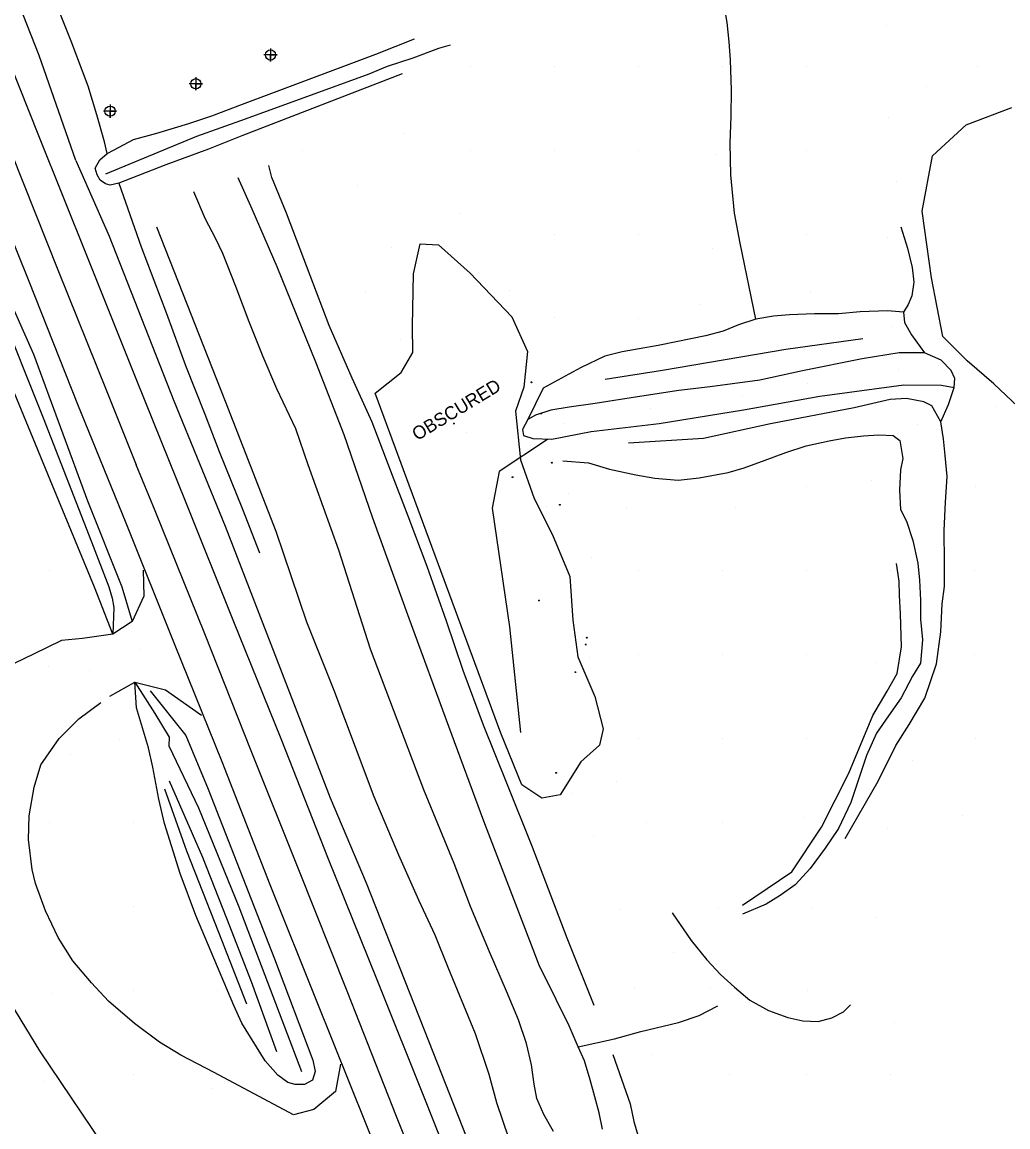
# Model space of a CAD drawing. Extents: x 524772 to 528246, y 273285 to 283088.
# Drawn here: x 527735.4 to 527849.8, y 274392.5 to 274520.7 of the extents above; entities that cross this region are included whole.
import ezdxf

# ---------------------------------------------------------------- set-up
doc = ezdxf.new("R2010")
doc.units = 0
for name, color, linetype in [('Exist DTM Breakline', 7, 'Continuous'), ('Exist DTM Crownline', 7, 'Continuous'), ('Exist DTM Regular Point CELL', 7, 'Continuous'), ('Exist Roads EOP', 7, 'Continuous'), ('Exist Roads Soil', 7, 'Continuous'), ('PH Exist DTM Breakline', 7, 'Continuous'), ('PH Exist DTM Obscure Area', 7, 'Continuous'), ('PH Exist DTM Obscure Area Text', 7, 'Continuous'), ('PH Exist DTM Point', 7, 'Continuous')]:
    doc.layers.add(name, color=color, linetype=linetype)

# ---------------------------------------------------------------- blocks, each defined once
blk = doc.blocks.new('EXIST DTM REGULAR POINT')
at = {"layer": 'Exist DTM Regular Point CELL'}
blk.add_lwpolyline([(0, 0.00152), (0, -0.00152), (0, 0), (0.00152, 0), (-0.00152, 0)], dxfattribs=at)
blk.add_circle((0, 0), 0.00119, dxfattribs=at)

msp = doc.modelspace()

# ---------------------------------------------------------------- linework, layer by layer
at = {"layer": 'Exist DTM Breakline'}
for points in [[(527796.38, 274472.24), (527790.75, 274468.51), (527789.94, 274464.27)], [(527789.94, 274464.27), (527791.97, 274450.5), (527793.25, 274438.22)]]:
    msp.add_lwpolyline(points, dxfattribs=at)
at = {"layer": 'Exist DTM Crownline'}
for points in [[(527645.29, 274728.71), (527650.66, 274714.78), (527656.2, 274701.14), (527661.92, 274686.83), (527667.92, 274671.8), (527673.23, 274658.53), (527678.79, 274644.52), (527684.53, 274630.14), (527690.01, 274616.33), (527695.81, 274601.85), (527701.46, 274587.58), (527706.7, 274574.49), (527712.09, 274560.76), (527717.61, 274547.05), (527723.18, 274532.85), (527728.56, 274519.55), (527734.18, 274505.53), (527739.64, 274491.72), (527745.18, 274477.97), (527748.66, 274469.27)], [(527812.62, 274309.15), (527807.09, 274323.12), (527801.45, 274337.52), (527795.99, 274351.2), (527790.12, 274365.72), (527784.37, 274379.82), (527778.84, 274393.65), (527773.12, 274408.21), (527767.53, 274422.3), (527762, 274436.08), (527756.61, 274449.67), (527750.87, 274463.93), (527748.66, 274469.27)]]:
    msp.add_lwpolyline(points, dxfattribs=at)
at = {"layer": 'Exist Roads EOP'}
for points in [[(527748.73, 274479.07), (527743.01, 274493.36), (527737.36, 274507.44), (527731.71, 274521.56), (527726.71, 274534.12), (527721.09, 274548.21), (527715.44, 274562.4), (527710.05, 274576.02), (527704.67, 274589.46), (527699.11, 274603.25), (527693.43, 274617.43), (527687.81, 274631.65), (527682.17, 274645.88), (527676.6, 274659.84), (527670.89, 274674.09), (527665.32, 274688.05), (527659.56, 274702.45), (527654.06, 274716.02), (527648.34, 274730.37)], [(527808.82, 274308.77), (527803.4, 274322.05), (527797.76, 274336.55), (527792.33, 274350.25), (527786.57, 274364.63), (527781, 274378.67), (527775.35, 274392.79), (527769.66, 274406.93), (527764.22, 274420.54), (527758.62, 274434.8), (527753.2, 274448.32), (527747.5, 274462.52), (527741.9, 274476.29), (527736.23, 274490.54), (527730.55, 274504.58)], [(527863.89, 274191.51), (527862.12, 274195.56), (527861.19, 274196.14), (527859.74, 274198.94), (527854.35, 274213.12), (527848.92, 274227.38), (527843.58, 274240.81), (527838, 274255.12), (527832.68, 274268.57), (527827.21, 274282.4), (527821.56, 274296.66), (527815.92, 274310.87), (527810.35, 274324.86), (527804.78, 274338.91), (527799.29, 274352.72), (527793.54, 274366.95), (527787.87, 274381.23), (527782.28, 274395.33), (527776.62, 274409.52), (527770.97, 274423.52), (527765.47, 274437.47), (527760, 274451.08), (527754.4, 274465.08), (527748.73, 274479.07)]]:
    msp.add_lwpolyline(points, dxfattribs=at)
at = {"layer": 'Exist Roads Soil'}
for points in [[(527749.48, 274457.07), (527749.53, 274454.03), (527748.19, 274451.11), (527745.95, 274449.62), (527742.42, 274449.14)], [(527745.62, 274442.45), (527748.5, 274444.07), (527752.05, 274443.17), (527756.22, 274440.23)], [(527772.34, 274399.73), (527771.78, 274396.58), (527769.28, 274394.47), (527766.92, 274393.87)]]:
    msp.add_lwpolyline(points, dxfattribs=at)
at = {"layer": 'PH Exist DTM Breakline'}
for points in [[(527741.66, 274504.6), (527737.42, 274516.78), (527732.32, 274529.71), (527724.98, 274549.13), (527719.16, 274564.36), (527715.63, 274574.32), (527714.55, 274578.02), (527714.19, 274580.1), (527714.39, 274581.73), (527715.05, 274582.71), (527716.82, 274583.67), (527718.28, 274584.2), (527720.91, 274585.38), (527723.64, 274586.58)], [(527745.28, 274505.39), (527744.98, 274506.77), (527744.1, 274509.9), (527743.08, 274513.22), (527741.13, 274518.46), (527738.24, 274525.64), (527734.35, 274535.54), (527730.94, 274544.61), (527727.68, 274553.41), (527726.25, 274556.28), (527724.49, 274560.38), (527723.03, 274564.1), (527720.19, 274571.56), (527718.74, 274575.3), (527717.87, 274577.77), (527716.43, 274581.79), (527718.46, 274581.99), (527720.51, 274582.88), (527722.97, 274584.16), (527725.86, 274585.71)], [(527820.55, 274486.19), (527818.7, 274495.02), (527818.05, 274498.49), (527817.62, 274502.95), (527817.57, 274506.62), (527817.67, 274509.73), (527817.72, 274512.76), (527817.58, 274516.27), (527817.43, 274518.35), (527817.22, 274520.62), (527816.77, 274523.11), (527816.33, 274524.99), (527814.49, 274529.02), (527811.56, 274528.34), (527809.89, 274528.93), (527808.04, 274529.6), (527806.16, 274530.8), (527805.12, 274532.08), (527803.75, 274534.22), (527803, 274535.66), (527802.46, 274537.88), (527802.67, 274539.74), (527803.88, 274542.26), (527804.37, 274544.34)], [(527779.53, 274514.64), (527760.92, 274507.45), (527757.06, 274505.92), (527752.1, 274504.09), (527746.66, 274501.98), (527745.64, 274501.75), (527745.09, 274501.87), (527744.5, 274502.33), (527744.15, 274502.92), (527743.9, 274503.72), (527744.43, 274504.68), (527745.28, 274505.39), (527746.1, 274505.85), (527748.34, 274507.02), (527751.07, 274507.78), (527754.75, 274508.9), (527757.45, 274509.78), (527761.01, 274511.14), (527776.46, 274516.94), (527780.96, 274518.72)], [(527785.06, 274517.97), (527783.71, 274517.6), (527780.75, 274516.49), (527777.79, 274515.5), (527775.63, 274514.62), (527761.29, 274509.4), (527755.66, 274507.4), (527745.1, 274503.01)], [(527741.66, 274504.6), (527745.51, 274495.8), (527753.01, 274476.72), (527758.97, 274462.16), (527764.73, 274447.27), (527771.16, 274430.65), (527775.35, 274420.77), (527782.56, 274402.44), (527787.94, 274388.77), (527793.91, 274373.37), (527798.61, 274361.95), (527803.2, 274350.89), (527807.64, 274339.89), (527811.88, 274328.63), (527815.94, 274318.47), (527823.29, 274299.84), (527830.72, 274280.05), (527835.27, 274267.52), (527840.2, 274254.37)], [(527801.79, 274406.55), (527798.66, 274414.34), (527794.62, 274424.93), (527791.66, 274432.35), (527788.96, 274439.07), (527786.57, 274445.41), (527784.66, 274451.14), (527782.4, 274457.48), (527780.19, 274463.33), (527778.19, 274468.53), (527776.05, 274474.22), (527773.73, 274479.33), (527771.03, 274485.44), (527768.84, 274491.27), (527766.08, 274498.5), (527764.4, 274502.64), (527764.05, 274504.02)], [(527802.76, 274392.18), (527802.36, 274394.1), (527801.86, 274395.95), (527801.32, 274397.92), (527800.65, 274400.11), (527799.93, 274401.75), (527798.87, 274404.17), (527797.37, 274407.23), (527795.41, 274411.22), (527793.44, 274416.38), (527789, 274427.94), (527784.94, 274438.9), (527780.34, 274451.46), (527776.1, 274463.08), (527772.77, 274472.77), (527769.5, 274481.21), (527765, 274492.25), (527762.11, 274498.93), (527760.49, 274502.59)], [(527746.66, 274501.98), (527749.24, 274494.57), (527752.19, 274486.83), (527754.37, 274480.79), (527756.62, 274475.16), (527758.3, 274470.84), (527761, 274464.14), (527762.98, 274459.08)], [(527797.08, 274391.94), (527795.95, 274393.91), (527795.15, 274395.76), (527794.82, 274397.43), (527794.5, 274399.65), (527793.93, 274402.14), (527793, 274404.89), (527791.62, 274408.2), (527789.66, 274412.77), (527787.44, 274418.02), (527785.56, 274423.03), (527782.03, 274431.58), (527775.85, 274447.88), (527772.15, 274459.36), (527768.61, 274469.3), (527767.17, 274473.46), (527764.99, 274478.09), (527763.38, 274481.8), (527761.75, 274485.89), (527760.21, 274489.98), (527758.71, 274493.81), (527757.86, 274495.57), (527756.7, 274497.77), (527755.36, 274500.97)], [(527751, 274496.89), (527758.98, 274476.65), (527764.86, 274461.6), (527768.43, 274451.08), (527771.59, 274443.13), (527774.07, 274436.55), (527776.23, 274430.79), (527779.07, 274424.01), (527781.41, 274418.81), (527783.3, 274414.75), (527784.79, 274410.99), (527787.97, 274403.29), (527789.56, 274398.56), (527790.44, 274395.28), (527791.86, 274391.18)], [(527837.36, 274496.91), (527838.11, 274494.43), (527838.68, 274492.18), (527838.87, 274490.47), (527838.61, 274488.88), (527838.21, 274487.9), (527837.67, 274487.01), (527837.76, 274485.8), (527838.59, 274484.38), (527840.08, 274482.29)], [(527732.08, 274492.62), (527736.74, 274482.12), (527743.01, 274465.09), (527746.98, 274455.14), (527748.19, 274451.11)], [(527732.62, 274487.79), (527737.87, 274474.74), (527743.49, 274460.33), (527745.47, 274455.13), (527745.88, 274453.82), (527746.05, 274452.74), (527745.95, 274449.62), (527743.83, 274455.09), (527738.96, 274466.89), (527732.25, 274483.04)], [(527837.67, 274487.01), (527835.81, 274487.16), (527832.63, 274487.02), (527830.13, 274486.81), (527827.32, 274486.79), (527824.45, 274486.7), (527822.59, 274486.55), (527820.55, 274486.19), (527818.53, 274485.51), (527816.75, 274484.81), (527814.7, 274484.26), (527811.31, 274483.57), (527809.2, 274483.11), (527806.99, 274482.74), (527805.01, 274482.39), (527803.02, 274481.9), (527800.26, 274480.56), (527798.86, 274479.8), (527795.87, 274478.17), (527794.09, 274474.55)], [(527803.05, 274479.24), (527809.69, 274480.25), (527824, 274482.7), (527832.96, 274483.96)], [(527843.55, 274478.27), (527843.6, 274479.29), (527843.19, 274480.21), (527842.01, 274481.43), (527840.08, 274482.29), (527837.15, 274482.26), (527832.87, 274481.6), (527825.96, 274480.18), (527821, 274479.1), (527815.25, 274478.32), (527811.6, 274477.92), (527806.8, 274477.19), (527801.88, 274476.41), (527798.88, 274475.99), (527796.74, 274475.62), (527794.98, 274475.05), (527794.09, 274474.55), (527793.45, 274473.38), (527793.59, 274472.69), (527794.65, 274472.32), (527796.86, 274472.25), (527801.44, 274473.14), (527809.33, 274474.09), (527819.11, 274475.68), (527827.94, 274477.25), (527837.71, 274478.57), (527842.06, 274478.51), (527843.55, 274478.27)], [(527841.98, 274474.27), (527842.87, 274476.27), (527843.55, 274478.27)], [(527830.89, 274425.91), (527834.71, 274432.56), (527836.78, 274436.72), (527838.31, 274439.16), (527840.14, 274442.22), (527841.48, 274446.17), (527842, 274449.92), (527842.15, 274453.15), (527842.41, 274455.15), (527842.43, 274457.95), (527842.36, 274461.66), (527842.53, 274464.95), (527842.73, 274467.92), (527842.5, 274470.35), (527842.3, 274472.3), (527841.98, 274474.27), (527840.96, 274476.12), (527840.02, 274476.58), (527838.02, 274476.98), (527836.13, 274476.86), (527831.93, 274475.9), (527822.22, 274474.02), (527814.47, 274472.35), (527805.77, 274471.81)], [(527798.14, 274469.76), (527801.14, 274469.53), (527803.56, 274468.79), (527806.63, 274468.13), (527808.81, 274467.72), (527811.53, 274467.49), (527813.96, 274467.78), (527817.33, 274468.41), (527819.16, 274468.93), (527821.62, 274469.84), (527824.02, 274470.71), (527826.37, 274471.49), (527829.04, 274472.07), (527830.95, 274472.4), (527833.03, 274472.63), (527834.8, 274472.75), (527836.48, 274472.69), (527837.23, 274472.12), (527837.59, 274470.01), (527837.33, 274468.72), (527837.21, 274466.34), (527837.3, 274464.11), (527838.01, 274462.76), (527838.74, 274460.51), (527839.32, 274457.87), (527839.52, 274455.9), (527839.62, 274453.58), (527839.64, 274451.39), (527839.86, 274448.99), (527839.63, 274446.28), (527838.69, 274444.74), (527837.37, 274442.23), (527835.93, 274440.16), (527834.52, 274438.15), (527833.35, 274435.55), (527831.55, 274430.11), (527830.13, 274427.09), (527828.58, 274424.78), (527826.84, 274422.45), (527825.11, 274420.56), (527823.35, 274419.3), (527821.73, 274418.29), (527818.98, 274417.14)], [(527818.97, 274418.19), (527824.71, 274422.04), (527828.16, 274427.25), (527831.3, 274433.52), (527834.12, 274440.2), (527835.76, 274443.03), (527836.94, 274445.05), (527837.41, 274448.16), (527837.33, 274452.01), (527837.21, 274454.14), (527837.16, 274455.79), (527836.86, 274457.83)], [(527742.42, 274449.14), (527739.98, 274448.89), (527736.77, 274447.3), (527733.46, 274445.72)], [(527748.5, 274444.07), (527750.84, 274440.43), (527752.5, 274437.68), (527752.46, 274436.67), (527755.9, 274429.47), (527760.57, 274418.01), (527767.82, 274398.89)], [(527750.29, 274443.07), (527754.42, 274437.86), (527757.01, 274431.65), (527764.71, 274411.94), (527769.15, 274400.21), (527769.44, 274398.9), (527769.11, 274397.87), (527768.18, 274397.36), (527767.1, 274397.37), (527766.25, 274397.59), (527765.09, 274398.44), (527763.62, 274400.12), (527760.92, 274404.5), (527759.99, 274406.53), (527758.11, 274411.02), (527755.59, 274416.98), (527753.76, 274421.86), (527751.95, 274427.66), (527751.28, 274430.49), (527750.58, 274434.21), (527750.1, 274436.44), (527748.71, 274441.07), (527748.5, 274444.07)], [(527766.92, 274393.87), (527757.69, 274398.75), (527753.85, 274400.78), (527751.36, 274402.3), (527748.48, 274404.45), (527745.44, 274407.03), (527743.49, 274409.16), (527741.3, 274411.74), (527739.62, 274414.43), (527738.16, 274417.53), (527736.98, 274420.71), (527736.61, 274422.34), (527736.17, 274425.79), (527736.25, 274428.56), (527736.82, 274431.88), (527737.62, 274434.48), (527739.72, 274437.53), (527742.01, 274439.81), (527744.56, 274441.7)], [(527761.48, 274406.71), (527758.25, 274415.03), (527754.55, 274424.46), (527751.98, 274431.65)], [(527752.49, 274432.63), (527756.34, 274423.75), (527759.12, 274416.68), (527761.99, 274409.31), (527764.94, 274401.21)], [(527810.82, 274417.29), (527813.02, 274414.07), (527814.85, 274411.84), (527816.42, 274410.12), (527818.04, 274408.66), (527819.84, 274407.17), (527822, 274405.95), (527824.25, 274405.14), (527825.98, 274404.76), (527827.75, 274404.67), (527829.33, 274405.1), (527830.69, 274405.79), (527831.53, 274406.62)], [(527733.01, 274408.61), (527737.43, 274401.29), (527745.98, 274388.61)], [(527799.93, 274401.75), (527804.14, 274402.67), (527807.19, 274403.51), (527811.58, 274404.57), (527813.95, 274405.37), (527816.14, 274406.51)], [(527803.96, 274400.87), (527805.97, 274395.12), (527806.38, 274393.07), (527807.12, 274390.57), (527808.33, 274387.21), (527809.76, 274383.37), (527810.98, 274379.16), (527812.88, 274373.91), (527814.9, 274368.76), (527816.67, 274363.51), (527817.69, 274360.4), (527819.02, 274356.2), (527820.32, 274352.85), (527821.52, 274349.61), (527823.81, 274344.03), (527825.49, 274339.79), (527826.6, 274337.35), (527827.78, 274333.72), (527829.38, 274329.91), (527831.57, 274325.69), (527833.96, 274319.92)]]:
    msp.add_lwpolyline(points, dxfattribs=at)
at = {"layer": 'PH Exist DTM Obscure Area'}
for points in [[(527853.69, 274473.42), (527848.15, 274478.69), (527845.04, 274481.35), (527842.21, 274484.17), (527840.91, 274490.97), (527839.81, 274498.73), (527841.04, 274505.13), (527844.92, 274508.75), (527850.23, 274510.76)], [(527776.39, 274477.61), (527779.41, 274480.01), (527780.76, 274482.33), (527780.7, 274485.38), (527780.81, 274491.46), (527781.59, 274494.92), (527783.72, 274494.8), (527787.41, 274491.51), (527792.25, 274486.44), (527794.05, 274482.44), (527793.63, 274478.28), (527792.65, 274475.5), (527793.23, 274469.85), (527794.83, 274465.39), (527796.93, 274461.15), (527798.97, 274456.33), (527799.29, 274451.26), (527799.87, 274446.99), (527801.84, 274442.39), (527802.84, 274438.64), (527802.41, 274436.74), (527800.22, 274434.82), (527797.85, 274430.99), (527795.7, 274430.62), (527793.41, 274432.14), (527790.96, 274438.13), (527776.39, 274477.61)]]:
    msp.add_lwpolyline(points, dxfattribs=at)
at = {"layer": 'PH Exist DTM Point'}
for p, q in [((527835.71, 274520.28), (527835.71, 274520.28)), ((527787.42, 274515.56), (527787.42, 274515.56)), ((527797.17, 274515.56), (527797.17, 274515.56)), ((527806.93, 274515.56), (527806.93, 274515.56)), ((527816.68, 274515.56), (527816.68, 274515.56)), ((527826.43, 274515.56), (527826.43, 274515.56)), ((527846.23, 274515.46), (527846.23, 274515.46)), ((527840.33, 274513.16), (527840.33, 274513.16)), ((527835.95, 274509.63), (527835.95, 274509.63)), ((527779.79, 274507.72), (527779.79, 274507.72)), ((527767.91, 274505.8), (527767.91, 274505.8)), ((527787.42, 274505.8), (527787.42, 274505.8)), ((527797.19, 274505.81), (527797.19, 274505.81)), ((527806.93, 274505.8), (527806.93, 274505.8)), ((527816, 274505.28), (527816, 274505.28)), ((527826.43, 274505.8), (527826.43, 274505.8)), ((527836.88, 274502.11), (527836.88, 274502.11)), ((527774.31, 274501.65), (527774.31, 274501.65)), ((527786.21, 274498.44), (527786.21, 274498.44)), ((527797.15, 274496.04), (527797.15, 274496.04)), ((527806.93, 274496.05), (527806.93, 274496.05)), ((527826.43, 274496.05), (527826.43, 274496.05)), ((527778.3, 274494.45), (527778.3, 274494.45)), ((527815.54, 274494.41), (527815.54, 274494.41)), ((527835.75, 274495.66), (527835.75, 274495.66)), ((527775.21, 274489.36), (527775.21, 274489.36)), ((527791.94, 274489.55), (527791.94, 274489.55)), ((527826.88, 274489.37), (527826.88, 274489.37)), ((527814.02, 274487.83), (527814.02, 274487.83)), ((527797.19, 274486.32), (527797.19, 274486.32)), ((527806.9, 274486.31), (527806.9, 274486.31)), ((527836.26, 274485.33), (527836.26, 274485.33)), ((527779.32, 274483.78), (527779.32, 274483.78)), ((527837.11, 274480.29), (527837.11, 274480.29)), ((527826.5, 274478.68), (527826.5, 274478.68)), ((527818.99, 274477.35), (527818.99, 274477.35)), ((527808.31, 274475.87), (527808.31, 274475.87)), ((527848.48, 274476.01), (527848.48, 274476.01)), ((527798.24, 274474.08), (527798.24, 274474.08)), ((527839.23, 274473.99), (527839.23, 274473.99)), ((527787, 274473), (527787, 274473)), ((527826.43, 274466.79), (527826.43, 274466.79)), ((527833.91, 274467.47), (527833.91, 274467.47)), ((527845.99, 274466.76), (527845.99, 274466.76)), ((527798.82, 274465.91), (527798.82, 274465.91)), ((527796.2, 274464.42), (527796.2, 274464.42)), ((527805.48, 274464.17), (527805.48, 274464.17)), ((527818.14, 274464.3), (527818.14, 274464.3)), ((527801.44, 274458.53), (527801.44, 274458.53)), ((527738.63, 274457.03), (527738.63, 274457.03)), ((527806.93, 274457.03), (527806.93, 274457.03)), ((527816.68, 274457.03), (527816.68, 274457.03)), ((527826.43, 274457.03), (527826.43, 274457.03)), ((527836.19, 274457.03), (527836.19, 274457.03)), ((527845.94, 274457.03), (527845.94, 274457.03)), ((527749.02, 274447.86), (527749.02, 274447.86)), ((527806.93, 274447.28), (527806.93, 274447.28)), ((527816.68, 274447.28), (527816.68, 274447.28)), ((527826.43, 274447.28), (527826.43, 274447.28)), ((527845.94, 274447.28), (527845.94, 274447.28)), ((527738.47, 274445.88), (527738.47, 274445.88)), ((527801.21, 274446.92), (527801.21, 274446.92)), ((527834.4, 274446.4), (527834.4, 274446.4)), ((527743.29, 274445.38), (527743.29, 274445.38)), ((527746.7, 274437.44), (527746.7, 274437.44)), ((527806.93, 274437.53), (527806.93, 274437.53)), ((527816.68, 274437.53), (527816.68, 274437.53)), ((527826.41, 274437.52), (527826.41, 274437.52)), ((527845.96, 274437.53), (527845.96, 274437.53)), ((527740.99, 274435.64), (527740.99, 274435.64)), ((527838.69, 274434.92), (527838.69, 274434.92)), ((527804.35, 274432.52), (527804.35, 274432.52)), ((527771.16, 274430.65), (527771.16, 274430.65)), ((527799.32, 274431.12), (527799.32, 274431.12)), ((527738.66, 274427.75), (527738.66, 274427.75)), ((527748.4, 274427.77), (527748.4, 274427.77)), ((527807.8, 274427.74), (527807.8, 274427.74)), ((527816.68, 274427.77), (527816.68, 274427.77)), ((527826.04, 274428.3), (527826.04, 274428.3)), ((527844.5, 274428.63), (527844.5, 274428.63)), ((527835.84, 274427.03), (527835.84, 274427.03)), ((527801.65, 274426.26), (527801.65, 274426.26)), ((527748.4, 274418.02), (527748.4, 274418.02)), ((527804.74, 274417.7), (527804.74, 274417.7)), ((527816.25, 274417.9), (527816.25, 274417.9)), ((527827.11, 274417.85), (527827.11, 274417.85)), ((527834.48, 274416.72), (527834.48, 274416.72)), ((527810.93, 274412.73), (527810.93, 274412.73)), ((527806.42, 274408.54), (527806.42, 274408.54)), ((527815.23, 274408.68), (527815.23, 274408.68)), ((527738.95, 274407.93), (527738.95, 274407.93)), ((527748.4, 274408.27), (527748.4, 274408.27)), ((527758.12, 274408.25), (527758.12, 274408.25)), ((527826.54, 274408.32), (527826.54, 274408.32)), ((527836.66, 274404.59), (527836.66, 274404.59)), ((527808.6, 274400.86), (527808.6, 274400.86)), ((527748.4, 274398.51), (527748.4, 274398.51)), ((527817.45, 274398.51), (527817.45, 274398.51)), ((527826.46, 274398.5), (527826.46, 274398.5)), ((527836.16, 274398.53), (527836.16, 274398.53)), ((527738.07, 274397.72), (527738.07, 274397.72)), ((527757.57, 274396.89), (527757.57, 274396.89))]:
    msp.add_line(p, q, dxfattribs=at)

# ---------------------------------------------------------------- block references
at = {"layer": 'Exist DTM Regular Point CELL'}
for p, xscale, yscale in [((527764.24, 274516.84), 500, 500), ((527755.58, 274513.5), 500, 500), ((527745.63, 274510.32), 500, 500), ((527794.51, 274478.86), 38.1000762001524, 38.1000762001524), ((527795.65, 274475.23), 38.1000762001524, 38.1000762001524), ((527785.52, 274474.07), 38.1000762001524, 38.1000762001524), ((527796.88, 274469.53), 38.1000762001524, 38.1000762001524), ((527792.32, 274467.85), 38.1000762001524, 38.1000762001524), ((527797.79, 274464.65), 38.1000762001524, 38.1000762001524), ((527795.38, 274453.54), 38.1000762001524, 38.1000762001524), ((527800.8, 274448.43), 38.1000762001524, 38.1000762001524), ((527800.93, 274449.22), 38.1000762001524, 38.1000762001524), ((527799.6, 274445.22), 38.1000762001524, 38.1000762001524), ((527797.37, 274433.53), 38.1000762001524, 38.1000762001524)]:
    msp.add_blockref('EXIST DTM REGULAR POINT', p, dxfattribs=dict(at, xscale=xscale, yscale=yscale))

# ---------------------------------------------------------------- texts
at = {"layer": 'PH Exist DTM Obscure Area Text'}
msp.add_text('OBSCURED', height=1.524, rotation=31.339, dxfattribs=at).set_placement((527781.25, 274472.03))

doc.saveas('drawing.dxf')
